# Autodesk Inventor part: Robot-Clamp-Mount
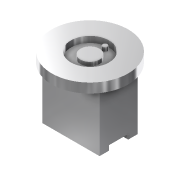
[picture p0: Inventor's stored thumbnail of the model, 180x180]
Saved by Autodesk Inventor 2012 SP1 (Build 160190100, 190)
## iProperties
Shininess: 21.0
Length Units: 11269
Angle Units: 11279
Time Units: 11290
Mass Units: 11283
Length Display Precision: 3
Angle Display Precision: 2
Created: 2001-08
Part Number: Robot-Clamp-Mount
Document SubType Name: ﾓﾃﾞﾘﾝｸﾞ
Designer: Administrator
Density: 1 g/cm^3
Material: Default
Density: 0.0
Volumn: 0.0
Area: 0.0
PropertySet Name: Model Information
Control State: 0
Master: False
Checked Out: False
Author: Administrator
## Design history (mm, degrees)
workplane "Work Plane1"
body "Solid1"
sketch "ｽｹｯﾁ1"
  geometry: C1 r 40 at (-1.046, 0.586)
  constraints: 1 centre point
  dimensions: "d0" = 80 diameter of C1
extrude "Extrusion1" new body sketch "ｽｹｯﾁ1" distance "d1" = 10; taper "d2" = 0 deg
sketch "ｽｹｯﾁ2"
  geometry: L1 (0, 15.75)-(0, 0); C1 r 40 at (0, 0) reference; C2 r 20 at (0, 0)
  constraints: 2 coincident, 2 end point, 1 centre point, 1 vertical
  dimensions: "d17" = 40 diameter of C2
extrude "Extrusion2" cut sketch "ｽｹｯﾁ2" distance "d7" = 6.5; taper "d8" = 0 deg
sketch "ｽｹｯﾁ3"
  geometry: L1 (-30, 20)-(30, 20); L2 (30, 20)-(30, -20); L3 (30, -20)-(-30, -20); L4 (-30, -20)-(-30, 20); L5 (-30, 0)-(30, 0); L6 (0, 20)-(0, -20); C1 r 40 at (0, 0) reference; 2 further points
  constraints: 12 end point, 5 midpoint, 2 coincident, 2 parallel, 1 horizontal, 1 perpendicular, 1 other
  dimensions: "d9" = 40 distance of L3.end L1.start; "d10" = 60 distance of L1.start L1.end
extrude "Extrusion3" join sketch "ｽｹｯﾁ3" distance "d11" = 60; taper "d12" = 0 deg
sketch "ｽｹｯﾁ4"
  geometry: L1 (-30, 20)-(30, 20) reference; L2 (-30, -20)-(-30, 20) reference; L3 (30, 20)-(30, -20) reference; L4 (-30, 10)-(30, 10); L5 (30, 10)-(30, -10); L6 (30, -10)-(-30, -10); L7 (-30, -10)-(-30, 10)
  constraints: 8 end point, 2 parallel, 2 point on line, 1 horizontal, 1 perpendicular
  dimensions: "d13" = 20 distance between parallel lines of L6 L4; "d14" = 10 distance between parallel lines of L4 L1
extrude "Extrusion4" cut sketch "ｽｹｯﾁ4" distance "d15" = 5; taper "d16" = 0 deg
sketch "ｽｹｯﾁ5"
  geometry: L1 (0, 0)-(0, 15.75); C1 r 20 at (0, 0) reference; C2 r 10 at (0, 0); C3 r 2.5 at (0, 15.75)
  constraints: 2 centre point, 2 coincident, 2 end point, 1 vertical
  dimensions: "d18" = 20 diameter of C2; "d19" = 15.75 distance of L1.start L1.end; "d20" = 5 diameter of C3
extrude "Extrusion5" join sketch "ｽｹｯﾁ5" distance "d21" = 4; taper "d22" = 0 deg
